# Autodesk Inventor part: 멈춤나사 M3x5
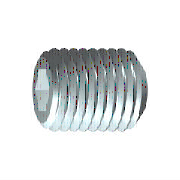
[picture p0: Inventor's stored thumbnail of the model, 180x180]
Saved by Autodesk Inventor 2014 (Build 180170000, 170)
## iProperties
Created: 2012-02
Part Number: 멈춤나사 M3x5
Material: 강철, 연강
Description: 6각 소켓 머리 없는 멈춤 나사
Document SubType Name: Modeling
Standard: KS B 1028
Designer: mduedu
Standards Organization: KS
Language: ko-KR
Size Designation: 납작점M3x5
Categories: <MemberInstance><Categories><Category DisplayName="조임쇠" InternalName="e4da775c-781d-43d5-af7c-5136215cf5a6" Mnemonic="FSTN"><Category DisplayName="볼트" InternalN
Density: 7.86 g/cm^3
Appearance: 노란색
Mass: 0.237668 g
Surface Area: 0.685518 cm^2
Volume: 0.0302376 cm^3
IsCustomPart: 1
Author: mduedu
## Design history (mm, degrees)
sketch "스케치1"
  geometry: L1 (0, 0)-(2.5, 0); L2 (5, 0.866)-(5, 1.5); L3 (5, 1.5)-(0, 1.5); L4 (5, 0.866)-(3, 0.866); L5 (3, 0.866)-(2.5, 0); L6 (0, -0.3)-(0, 1.8) reference; L7 (0, 1.5)-(0, 0)
  constraints: 13 end point, 3 parallel, 1 collinear, 1 perpendicular, 1 point on line
  dimensions: "d0" = 2 distance of L2.start L4.end (= INTI); "d1" = 60 deg angle of L5 L1; "d2" = 3 diameter of L3 L1 (= NND); "d3" = 1.73205 diameter of L4 L1 (= 1.1547 x SW); "d5" = 5 distance from line of L2 L3.end (= NLG)
revolve "본체" sketch "스케치1" stored, may be unused: angle "d6" = 90 deg
sketch "스케치2"
  geometry: L1 (-0.433, 0.75)-(0.433, 0.75); L2 (0.433, 0.75)-(0.866, 0); L3 (0.866, 0)-(0.433, -0.75); L4 (0.433, -0.75)-(-0.433, -0.75); L5 (-0.433, -0.75)-(-0.866, 0); L6 (-0.866, 0)-(-0.433, 0.75); A1 r 0.866 centre (0, 0) between (-0.433, 0.75) and (0.433, 0.75) reference; 2 further points
  constraints: 12 end point, 2 point on circle, 1 coincident, 1 horizontal, 11 other
extrude "슬롯" join sketch "스케치2" taper "d9" = 0 deg; stored distance "d21" = 10
workaxis "Work Axis1"
workplane "Work Plane1"
body "Solid1"
chamfer "모따기1" distance "d7" = 0.30673 (= -0.5 x GD1 + 0.5 x NND); stored, may be unused: angle "d8" = 45 deg (= FAWI), second distance "d29" = 0.30673 (= -0.5 x GD1 + 0.5 x NND)
feature "스레드" dims "d11" = 5 (= NLG), "d12" = 0
chamfer "모따기2" distance "d13" = 0.30673 (= -0.5 x GD1 + 0.5 x NND); stored, may be unused: angle "d14" = 45 deg (= FAWI), second distance "d30" = 0.30673 (= -0.5 x GD1 + 0.5 x NND)
other parameters: "NND" = 3 [user parameter; used in 5 equation terms], "NLG" = 5 [user parameter; used in 2 equation terms], "INTI" = 2 [user parameter; used in 1 equation term], "FAWI" = 45 deg [user parameter; used in 2 equation terms], "SW" = 1.5 [user parameter; used in 2 equation terms], "GD1" = 2.38655 (= THREADDIA - 1.2269 x PTC) [user parameter; used in 4 equation terms], "d4" = 0, "FAWI1" = 45 deg [user parameter], "d15" = 0, "d31" = 0, "GUL" = 0.30673 (= 0.61345 x PTC) [user parameter], "SPD" = 2 [user parameter], "TOA" = 30 deg [user parameter], "THREADDIA" = 3 [user parameter; used in 1 equation term], "PTC" = 0.5 [user parameter; used in 4 equation terms], "GAL" = 0.30673 (= 0.61345 x PTC) [user parameter], "E0" = 1.7325 (= 1.155 x SW) [user parameter]
